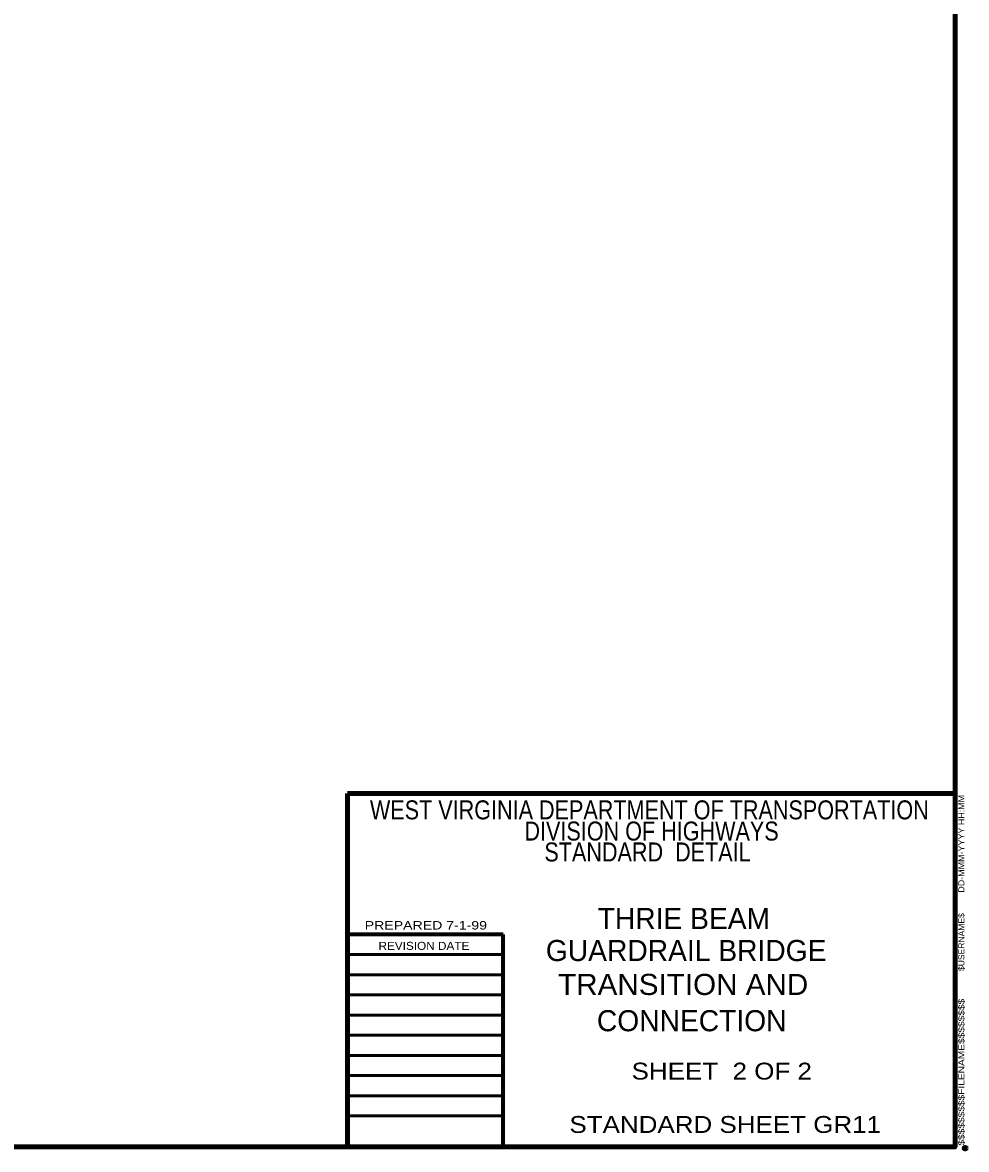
# Model space of a CAD drawing. Extents: x 895.6 to 930.4, y -2278.6 to -2254.7.
# Drawn here: x 920.73 to 930.05, y -2277.19 to -2266.06 of the extents above; entities that cross this region are included whole.
import ezdxf
from ezdxf.enums import TextEntityAlignment as Align

# ---------------------------------------------------------------- set-up
doc = ezdxf.new("R2010")
doc.units = 0
doc.header["$LTSCALE"] = 0.051
doc.header["$PDMODE"] = 32
doc.header["$PDSIZE"] = 0.0255
for name, color, linetype, lineweight in [('1', 7, 'Continuous', 70), ('3', 7, 'Continuous', 40), ('5', 7, 'Continuous', 25)]:
    doc.layers.add(name, color=color, linetype=linetype, lineweight=lineweight)

msp = doc.modelspace()

# ---------------------------------------------------------------- linework, layer by layer
at = {"layer": '1'}
msp.add_point((930.04183, -2277.17517), dxfattribs=at)
at = {"layer": '3', "lineweight": 106}
for p in [(929.94183, -2273.6735), (923.94183, -2277.16333)]:
    msp.add_line(p, (923.94183, -2273.6735), dxfattribs=at)
at = {"layer": '3', "lineweight": 53}
for p, q in [((929.94183, -2277.16333), (929.94183, -2274.66433)), ((925.47975, -2275.26433), (923.94183, -2275.26433)), ((925.47975, -2275.46333), (923.94183, -2275.46333)), ((925.47975, -2275.66233), (923.94183, -2275.66233)), ((923.94183, -2275.75333), (923.94183, -2277.16333)), ((925.47975, -2275.86133), (923.94183, -2275.86133)), ((925.47975, -2276.06033), (923.94183, -2276.06033)), ((925.47975, -2276.25933), (923.94183, -2276.25933)), ((925.47975, -2276.45833), (923.94183, -2276.45833)), ((925.47975, -2276.65733), (923.94183, -2276.65733)), ((925.47975, -2276.85633), (923.94183, -2276.85633)), ((929.94183, -2277.16333), (923.94183, -2277.16333))]:
    msp.add_line(p, q, dxfattribs=at)
at = {"layer": '3', "lineweight": 70}
for p, q in [((925.47975, -2275.06433), (923.94183, -2275.06433)), ((925.47975, -2277.16333), (925.47975, -2275.06433))]:
    msp.add_line(p, q, dxfattribs=at)
at = {"layer": '3', "lineweight": 158}
msp.add_lwpolyline([(929.94183, -2256.16333), (929.94183, -2277.16333), (897.44183, -2277.16333)], dxfattribs=at)
at = {"layer": '3'}
msp.add_point((929.94183, -2277.16333), dxfattribs=at)

# ---------------------------------------------------------------- texts
at = {"layer": '1'}
for s, width, p in [('DD-MMM-YYYY HH:MM', 1.1, (930.03408, -2274.65233)), ('$USERNAME$', 1.05, (930.03408, -2275.42592)), ('$$$$$$$$$FILENAME$$$$$$$$', 1.25, (930.03408, -2277.15))]:
    msp.add_text(s, height=0.06, rotation=90, dxfattribs=dict(at, width=width)).set_placement(p)
at = {"layer": '3'}
for s, height, width, p in [('WEST VIRGINIA DEPARTMENT OF TRANSPORTATION', 0.1875, 0.85, (926.92358, -2273.92842)), ('DIVISION OF HIGHWAYS', 0.1875, 0.85, (926.94546, -2274.13733)), ('STANDARD  DETAIL', 0.1875, 0.85, (926.90554, -2274.34383)), ('PREPARED 7-1-99', 0.08333, 1.25, (924.71671, -2275.016)), (' SHEET  2 OF 2      ', 0.1667, 1.15, (927.81642, -2276.49758)), ('STANDARD SHEET GR11', 0.1667, 1.15, (927.67279, -2277.02458))]:
    msp.add_text(s, height=height, dxfattribs=dict(at, width=width)).set_placement(p, align=Align.CENTER)
at = {"layer": '3', "width": 1.1}
msp.add_text('REVISION DATE', height=0.079, dxfattribs=at).set_placement((924.24892, -2275.217))
at = {"layer": '5'}
for s, p in [('THRIE BEAM', (927.26412, -2275.01108)), ('GUARDRAIL BRIDGE', (927.28679, -2275.3275)), ('CONNECTION', (927.34175, -2276.02067))]:
    msp.add_text(s, height=0.2083, dxfattribs=at).set_placement(p, align=Align.CENTER)
at = {"layer": '5', "width": 1.05}
msp.add_text('TRANSITION AND', height=0.2083, dxfattribs=at).set_placement((927.25771, -2275.66242), align=Align.CENTER)

doc.saveas('drawing.dxf')
